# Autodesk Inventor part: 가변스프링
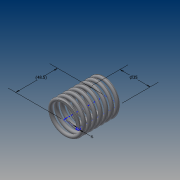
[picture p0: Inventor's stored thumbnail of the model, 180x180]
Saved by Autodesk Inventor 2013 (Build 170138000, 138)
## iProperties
Created: 2015-01
Part Number: 가변스프링
Material: 일반
Document SubType Name: Modeling
Designer: Administrator
Density: 1 g/cm^3
Author: Administrator
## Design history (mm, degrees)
sketch "스케치1"
  geometry: L1 (0, 0)-(17.5, 0); L2 (17.5, 0)-(17.5, 48.5); L3 (17.5, 48.5)-(0, 48.5); L4 (0, 48.5)-(0, 0); C1 r 2 at (17.5, 0)
  constraints: 8 end point, 2 parallel, 1 centre point, 1 coincident, 1 horizontal, 1 perpendicular
  dimensions: "d0" = 48.5 distance of L3.end L1.start (derived); "d1" = 35 diameter of L2 L4; "d2" = 4 diameter of C1
feature "코일1" pitch "d3" = 10; turns "d5" = 7.5; dims "d4" = 48.5 (= d0), "d6" = 0, angle "d7" = 90 deg, angle "d8" = 90 deg, "d9" = 0, "d10" = 0
node "작업 평면1"
sketch "스케치2"
  geometry: L1 (33, 0)-(37, 0) reference; 1 further point
  constraints: 1 horizontal alignment
extrude "돌출1" cut sketch "스케치2" stored distance "d12" = 10; taper "d13" = 0 deg
node "작업 평면2"
sketch "스케치3"
  geometry: L1 (15.5, 0)-(19.5, 0) reference; 1 further point
  constraints: 1 horizontal alignment
extrude "돌출2" cut sketch "스케치3" stored distance "d15" = 10; taper "d16" = 0 deg
node "솔리드1"
node "절단 모서리 투영1"
node "절단 모서리 투영2"
other parameters: "d11" = 90 deg, "d14" = 90 deg
